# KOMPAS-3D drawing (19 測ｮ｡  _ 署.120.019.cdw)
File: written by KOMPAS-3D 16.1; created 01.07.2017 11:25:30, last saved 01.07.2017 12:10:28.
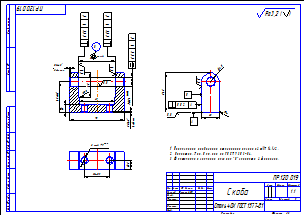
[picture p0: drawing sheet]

Sheet 1: A3, landscape

Title block, sheet 1: name: Скоба; designation: ПР.120.019; material: Сталь 40Х ГОСТ 1577-81; scale: 1:1; sheets: 1; sheet format: A3; stored path: G:\VSE\Донецк\Прохвост\KOMPAS v16.1\19 Скоба _ К17.479.019.cdw; drawn by: Сигачев СИ

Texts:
  Sergey
  Неуказанные предельные отклонения размеров  (IT 14)/2.
  Покрытие: Хим. Окс. прм по ГОСТ 9.303-84.
  Фактическое значение размера "д" записать в формуляр.
  Ra3,2
  Ra3,2 ( )
Dimensions and other numbers on the sheet: 49; 0,5; 12; 75; 4 фаски; 10; 42±0,1; 35±0,1; 0,8; 2 фаски; 0,02; 50; 0,4; 12,5; 54,5; 25; 2 отв.; 9; 1:1; 1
